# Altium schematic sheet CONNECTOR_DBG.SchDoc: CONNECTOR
size A4; Revision: V2.0; SheetNumber: 6; SheetTotal: 7; Project: PY32F403v1xT_START
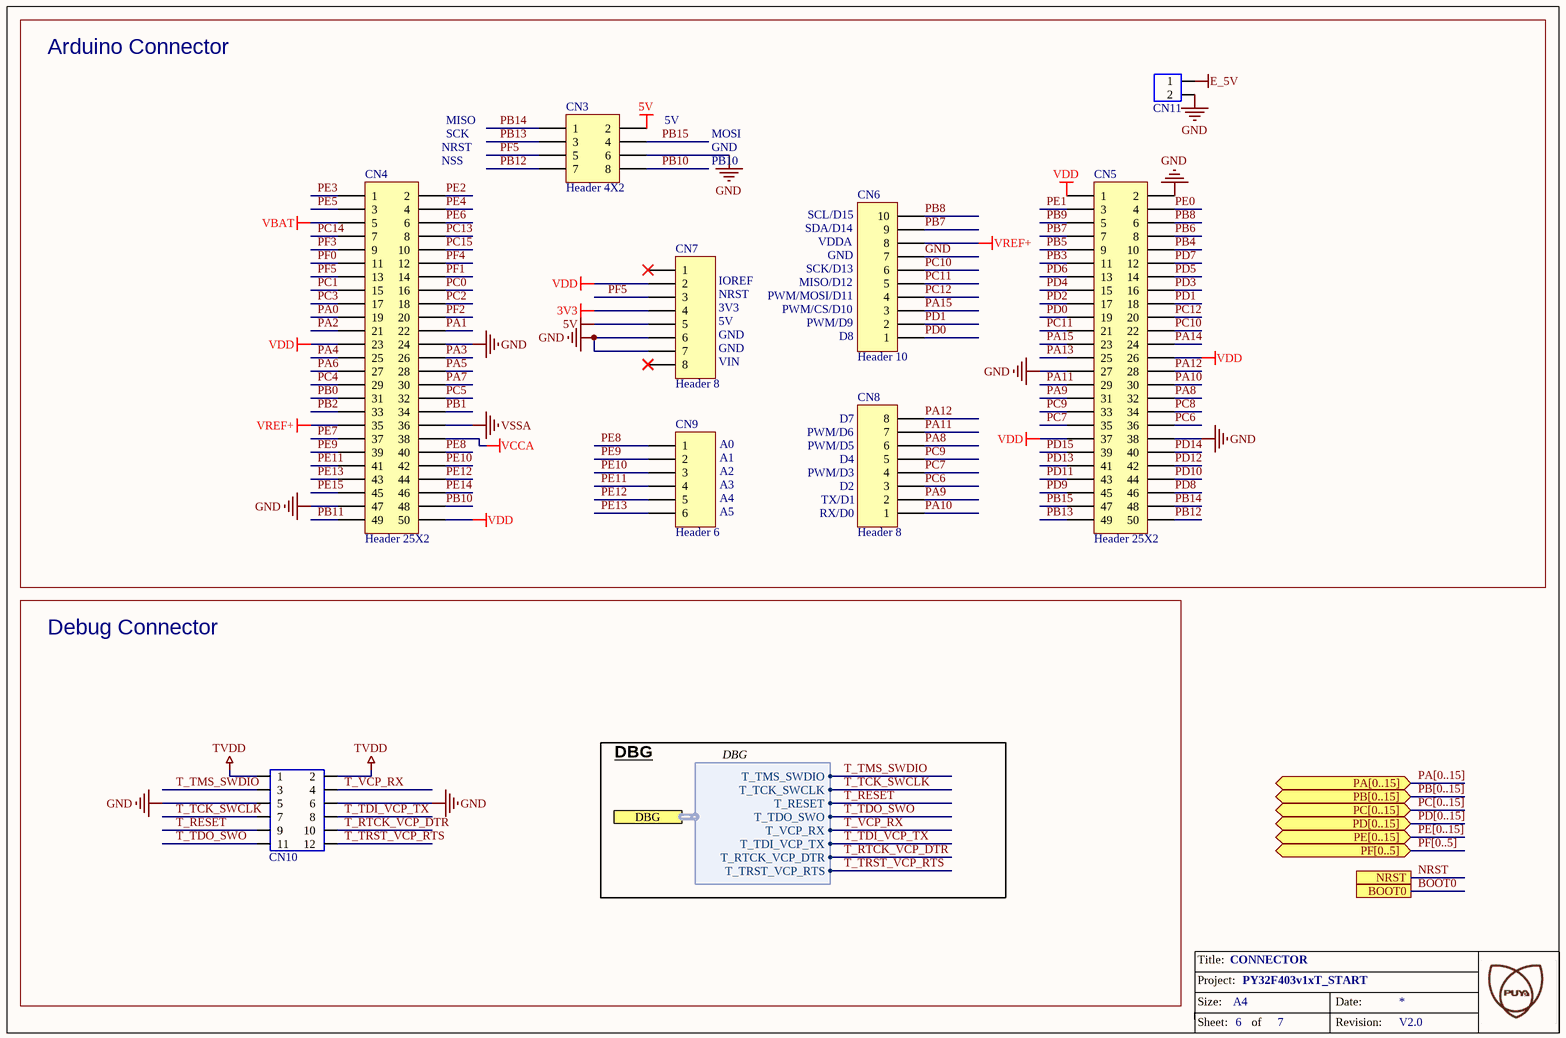
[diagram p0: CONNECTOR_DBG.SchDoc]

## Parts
CN3  Header 4X2  [HDR2X4]
CN4  Header 25X2  [HDR2X25]
CN5  Header 25X2  [HDR2X25]
CN6  Header 10  [1*10P_FEMALE]
CN7  Header 8  [1*8P_FEMALE]
CN8  Header 8  [1*8P_FEMALE]
CN9  Header 6  [1*6P_FEMALE]
CN10  CON6x2  [CON6x2]  (value not drawn)
CN11  CON2  [CON2]  (value not drawn)

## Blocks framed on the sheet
Arduino Connector: CN3-CN9 CN11
Debug Connector: CN10

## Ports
BOOT0, DBG (harness DBG), NRST, PA[0..15] (bidir), PB[0..15] (bidir), PC[0..15] (bidir), PD[0..15] (bidir), PE[0..15] (bidir), PF[0..5] (bidir)

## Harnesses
DBG: T_VCP_RX, T_TDO_SWO, T_RESET, T_TMS_SWDIO, T_TDI_VCP_TX, T_TCK_SWCLK, T_RTCK_VCP_DTR, T_TRST_VCP_RTS

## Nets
3V3: CN7.4
5V: CN3.2 CN7.5
E_5V: CN11.1
GND: CN3.6 CN4.24 CN4.47 CN5.2 CN5.27 CN5.38 CN6.7 CN7.6 CN7.7 CN10.5 CN10.6 CN11.2
TVDD: CN10.1 CN10.2
VBAT: CN4.5
VCCA: CN4.38
VDD: CN4.23 CN4.50 CN5.1 CN5.26 CN5.37 CN7.2
VREF+: CN4.35 CN6.8
VSSA: CN4.36
PA0: CN4.19
PA1: CN4.22
PA2: CN4.21
PA3: CN4.26
PA4: CN4.25
PA5: CN4.28
PA6: CN4.27
PA7: CN4.30
PA8: CN5.32 CN8.6
PA9: CN5.31 CN8.2
PA10: CN5.30 CN8.1
PA11: CN5.29 CN8.7
PA12: CN5.28 CN8.8
PA13: CN5.25
PA14: CN5.24
PA15: CN5.23 CN6.3
PB0: CN4.31
PB1: CN4.34
PB2: CN4.33
PB3: CN5.11
PB4: CN5.10
PB5: CN5.9
PB6: CN5.8
PB7: CN5.7 CN6.9
PB8: CN5.6 CN6.10
PB9: CN5.5
PB10: CN3.8 CN4.48
PB11: CN4.49
PB12: CN3.7 CN5.50
PB13: CN3.3 CN5.49
PB14: CN3.1 CN5.48
PB15: CN3.4 CN5.47
PC0: CN4.16
PC1: CN4.15
PC2: CN4.18
PC3: CN4.17
PC4: CN4.29
PC5: CN4.32
PC6: CN5.36 CN8.3
PC7: CN5.35 CN8.4
PC8: CN5.34
PC9: CN5.33 CN8.5
PC10: CN5.22 CN6.6
PC11: CN5.21 CN6.5
PC12: CN5.20 CN6.4
PC13: CN4.8
PC14: CN4.7
PC15: CN4.10
PD0: CN5.19 CN6.1
PD1: CN5.18 CN6.2
PD2: CN5.17
PD3: CN5.16
PD4: CN5.15
PD5: CN5.14
PD6: CN5.13
PD7: CN5.12
PD8: CN5.46
PD9: CN5.45
PD10: CN5.44
PD11: CN5.43
PD12: CN5.42
PD13: CN5.41
PD14: CN5.40
PD15: CN5.39
PE0: CN5.4
PE1: CN5.3
PE2: CN4.2
PE3: CN4.1
PE4: CN4.4
PE5: CN4.3
PE6: CN4.6
PE7: CN4.37
PE8: CN4.40 CN9.1
PE9: CN4.39 CN9.2
PE10: CN4.42 CN9.3
PE11: CN4.41 CN9.4
PE12: CN4.44 CN9.5
PE13: CN4.43 CN9.6
PE14: CN4.46
PE15: CN4.45
PF0: CN4.11
PF1: CN4.14
PF2: CN4.20
PF3: CN4.9
PF4: CN4.12
PF5: CN3.5 CN4.13 CN7.3
T_RESET: CN10.9 ; port DBG.T_RESET
T_RTCK_VCP_DTR: CN10.10 ; port DBG.T_RTCK_VCP_DTR
T_TCK_SWCLK: CN10.7 ; port DBG.T_TCK_SWCLK
T_TDI_VCP_TX: CN10.8 ; port DBG.T_TDI_VCP_TX
T_TDO_SWO: CN10.11 ; port DBG.T_TDO_SWO
T_TMS_SWDIO: CN10.3 ; port DBG.T_TMS_SWDIO
T_TRST_VCP_RTS: CN10.12 ; port DBG.T_TRST_VCP_RTS
T_VCP_RX: CN10.4 ; port DBG.T_VCP_RX

Not connected (* = marked no-connect by the designer): CN7 1* 8*

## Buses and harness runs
bus PA[0..15] = port PA[0..15]
bus PB[0..15] = port PB[0..15]
bus PC[0..15] = port PC[0..15]
bus PD[0..15] = port PD[0..15]
bus PE[0..15] = port PE[0..15]
bus PF[0..5] = port PF[0..5]

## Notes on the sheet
- (near CN4) NRST
- (near CN4) NSS
- MISO
- SCK
- (near CN3) 5V
- MOSI
- GND
- PB10
- (near CN6) SDA/D14
- (near CN6) SCL/D15
- VDDA
- (near CN7) IOREF
- (near CN7) NRST
- (near CN7) 3V3
- PWM/MOSI/D11
- PWM/CS/D10
- (near CN6) MISO/D12
- (near CN6) SCK/D13
- (near CN6) GND
- (near CN7) 5V
- (near CN7) GND
- (near CN7) VIN
- PWM/D9
- (near CN6) D8
- (near CN9) A0
- PWM/D6
- PWM/D5
- (near CN8) D7
- (near CN9) A1
- (near CN9) A2
- (near CN9) A3
- (near CN9) A4
- (near CN9) A5
- (near CN8) PWM/D3
- (near CN8) RX/D0
- (near CN8) TX/D1
- (near CN8) D4
- (near CN8) D2
- DBG

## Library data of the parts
CN3 = Header 4X2: Header, 4-Pin, Dual row
CN4 CN5 = Header 25X2: Header, 25-Pin, Dual row
CN6 = Header 10: Header, 10-Pin
CN7 CN8 = Header 8: Header, 8-Pin
CN9 = Header 6: Header, 6-Pin
CN10 = CON6x2: PCB DECAL: CON5x2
